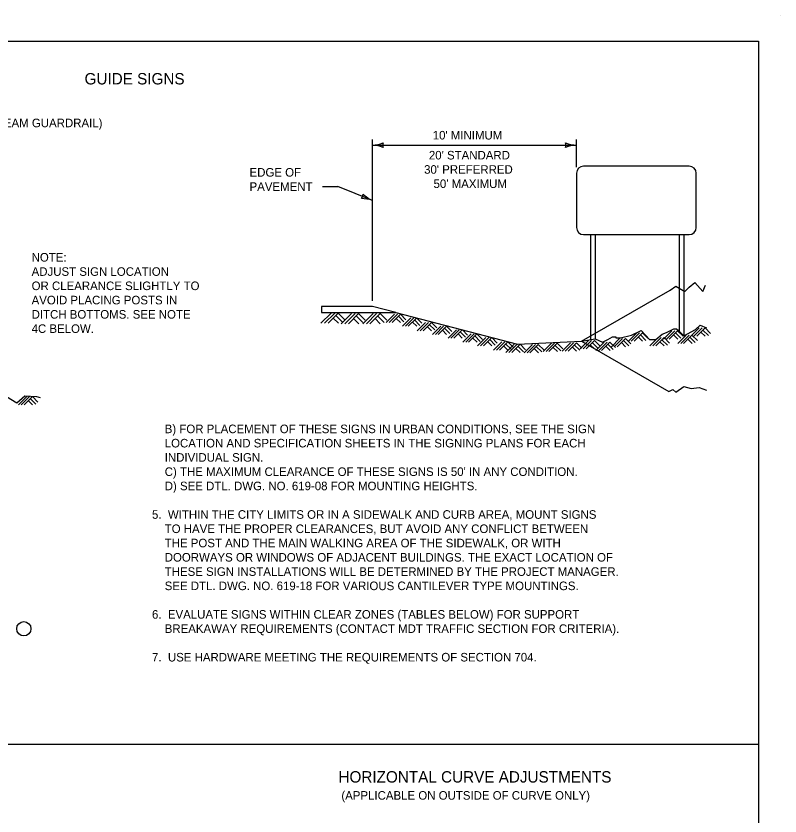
# Model space of a CAD drawing. Extents: x 49991.4 to 50021, y 49987.6 to 50011.4.
# Drawn here: x 50011.54 to 50016.9, y 49993.57 to 49999.18 of the extents above; entities that cross this region are included whole.
import ezdxf

# ---------------------------------------------------------------- set-up
doc = ezdxf.new("R2010")
doc.units = 0
for name, color, linetype in [('Level 1', 7, 'Continuous'), ('Level 2', 7, 'Continuous'), ('Level 3', 7, 'Continuous')]:
    doc.layers.add(name, color=color, linetype=linetype)

msp = doc.modelspace()

# ---------------------------------------------------------------- linework, layer by layer
at = {"layer": 'Level 1'}
for p, q in [((50016.9001, 49999.1756), (50016.9001, 49999.1756)), ((50016.263, 49998.1235), (50015.5229, 49998.1235)), ((50015.4729, 49998.0735), (50015.4729, 49997.6934)), ((50016.313, 49997.6934), (50016.313, 49998.0735)), ((50015.5229, 49997.6434), (50016.263, 49997.6434)), ((50015.5741, 49996.9115), (50015.5741, 49997.6434)), ((50015.6062, 49996.9147), (50015.6062, 49997.6434)), ((50016.1953, 49996.968), (50016.1953, 49997.6434)), ((50016.2274, 49996.9368), (50016.2274, 49997.6434)), ((50015.5091, 49996.8956), (50016.1291, 49997.2536)), ((50014.0419, 49997.1393), (50013.6857, 49997.1393)), ((50013.6857, 49997.1393), (50013.6857, 49997.0967)), ((50014.2056, 49997.0967), (50014.0419, 49997.1393)), ((50013.6806, 49997.022), (50013.7526, 49997.094)), ((50013.6857, 49997.0967), (50014.2058, 49997.0967)), ((50013.7059, 49997.022), (50013.7779, 49997.094)), ((50013.731, 49997.022), (50013.803, 49997.094)), ((50013.7853, 49997.0762), (50013.8321, 49997.0295)), ((50013.803, 49997.094), (50013.8499, 49997.0472)), ((50013.8231, 49997.019), (50013.8951, 49997.091)), ((50013.8484, 49997.019), (50013.9204, 49997.091)), ((50013.8735, 49997.019), (50013.9455, 49997.091)), ((50013.9455, 49997.091), (50013.9924, 49997.0442)), ((50013.9744, 49997.019), (50014.0464, 49997.091)), ((50013.9997, 49997.019), (50014.0717, 49997.091)), ((50014.0248, 49997.019), (50014.0968, 49997.091)), ((50014.0968, 49997.091), (50014.1437, 49997.0442)), ((50014.1395, 49997.0268), (50014.1978, 49997.0851)), ((50014.16, 49997.0268), (50014.2183, 49997.0851)), ((50014.1803, 49997.0268), (50014.2386, 49997.0851)), ((50014.2056, 49997.0967), (50014.2056, 49997.0967)), ((50014.2056, 49997.0967), (50015.0598, 49996.8746)), ((50014.2386, 49997.0851), (50014.2766, 49997.0472)), ((50013.7674, 49997.0583), (50013.8038, 49997.022)), ((50013.9099, 49997.0553), (50013.9463, 49997.019)), ((50013.9277, 49997.0732), (50013.9745, 49997.0265)), ((50014.0612, 49997.0553), (50014.0976, 49997.019)), ((50014.079, 49997.0732), (50014.1258, 49997.0265)), ((50014.2098, 49997.0563), (50014.2394, 49997.0268)), ((50014.2242, 49997.0708), (50014.2622, 49997.0329)), ((50014.2528, 49997.0015), (50014.3111, 49997.0598)), ((50014.2733, 49997.0015), (50014.3316, 49997.0598)), ((50014.2936, 49997.0015), (50014.3511, 49997.0589)), ((50014.3231, 49997.0309), (50014.3527, 49997.0015)), ((50014.3376, 49997.0455), (50014.3755, 49997.0076)), ((50014.3536, 49997.0582), (50014.3899, 49997.0219)), ((50014.3565, 49996.9699), (50014.4148, 49997.0282)), ((50014.377, 49996.9699), (50014.4353, 49997.0282)), ((50014.3973, 49996.9699), (50014.4556, 49997.0282)), ((50014.4556, 49997.0282), (50014.4936, 49996.9903)), ((50014.4268, 49996.9994), (50014.4563, 49996.9699)), ((50014.4413, 49997.0139), (50014.4792, 49996.976)), ((50014.4629, 49996.9437), (50014.5212, 49997.0021)), ((50014.4835, 49996.9437), (50014.5418, 49997.0021)), ((50014.5038, 49996.9437), (50014.5621, 49997.0021)), ((50014.5333, 49996.9731), (50014.5628, 49996.9437)), ((50014.5477, 49996.9877), (50014.5856, 49996.9498)), ((50014.5621, 49997.0021), (50014.6001, 49996.9641)), ((50014.5724, 49996.9186), (50014.6307, 49996.9769)), ((50014.5929, 49996.9186), (50014.6513, 49996.9769)), ((50014.6133, 49996.9186), (50014.6705, 49996.9758)), ((50014.6735, 49996.9751), (50014.7096, 49996.9391)), ((50016.0829, 49996.9118), (50016.1412, 49996.9701)), ((50016.1035, 49996.9118), (50016.1618, 49996.9701)), ((50016.1237, 49996.9118), (50016.1821, 49996.9701)), ((50016.1821, 49996.9701), (50016.2201, 49996.9322)), ((50016.2751, 49996.9309), (50016.3334, 49996.9892)), ((50016.2957, 49996.9309), (50016.354, 49996.9892)), ((50016.3159, 49996.9309), (50016.3743, 49996.9892)), ((50016.3599, 49996.9748), (50016.3978, 49996.937)), ((50016.3743, 49996.9892), (50016.4123, 49996.9513)), ((50014.6428, 49996.948), (50014.6722, 49996.9186)), ((50014.6572, 49996.9625), (50014.6951, 49996.9248)), ((50014.6759, 49996.8891), (50014.7342, 49996.9475)), ((50014.6965, 49996.8891), (50014.7548, 49996.9475)), ((50014.7167, 49996.8891), (50014.775, 49996.9475)), ((50014.7462, 49996.9186), (50014.7757, 49996.8891)), ((50014.7606, 49996.9331), (50014.7986, 49996.8952)), ((50014.775, 49996.9475), (50014.8131, 49996.9095)), ((50014.78, 49996.8635), (50014.8383, 49996.9218)), ((50014.8005, 49996.8635), (50014.8589, 49996.9218)), ((50014.8208, 49996.8635), (50014.879, 49996.9216)), ((50014.8795, 49996.9215), (50014.9172, 49996.8839)), ((50015.7175, 49996.8581), (50015.7758, 49996.9164)), ((50015.7381, 49996.8581), (50015.7964, 49996.9164)), ((50015.7583, 49996.8581), (50015.8167, 49996.9164)), ((50015.8167, 49996.9164), (50015.8547, 49996.8785)), ((50015.837, 49996.8963), (50015.8953, 49996.9546)), ((50015.8576, 49996.8963), (50015.9159, 49996.9546)), ((50015.8778, 49996.8963), (50015.9362, 49996.9546)), ((50015.9074, 49996.9257), (50015.9369, 49996.8963)), ((50015.9218, 49996.9402), (50015.9597, 49996.9024)), ((50015.9362, 49996.9546), (50015.9742, 49996.9167)), ((50015.9876, 49996.8633), (50016.0459, 49996.9216)), ((50016.0082, 49996.8633), (50016.0665, 49996.9216)), ((50016.0284, 49996.8633), (50016.0868, 49996.9216)), ((50016.0868, 49996.9216), (50016.1248, 49996.8837)), ((50016.1533, 49996.9412), (50016.1828, 49996.9118)), ((50016.1677, 49996.9557), (50016.2056, 49996.9179)), ((50016.1834, 49996.8807), (50016.2417, 49996.939)), ((50016.204, 49996.8807), (50016.2623, 49996.939)), ((50016.2242, 49996.8807), (50016.2826, 49996.939)), ((50016.2538, 49996.9101), (50016.2833, 49996.8807)), ((50016.2682, 49996.9246), (50016.3061, 49996.8868)), ((50016.2826, 49996.939), (50016.3206, 49996.9011)), ((50016.3455, 49996.9603), (50016.375, 49996.9309)), ((50014.8504, 49996.8929), (50014.8798, 49996.8635)), ((50014.8648, 49996.9074), (50014.9027, 49996.8696)), ((50014.8916, 49996.8339), (50014.9499, 49996.8922)), ((50014.9122, 49996.8339), (50014.9705, 49996.8922)), ((50014.9324, 49996.8339), (50014.9908, 49996.8922)), ((50014.962, 49996.8633), (50014.9915, 49996.8339)), ((50014.9764, 49996.8778), (50015.0143, 49996.84)), ((50014.9781, 49996.8167), (50015.0364, 49996.875)), ((50014.9908, 49996.8922), (50015.0288, 49996.8543)), ((50014.9987, 49996.8167), (50015.057, 49996.875)), ((50015.0189, 49996.8167), (50015.0773, 49996.875)), ((50015.0598, 49996.8746), (50015.5091, 49996.8956)), ((50015.0629, 49996.8606), (50015.1008, 49996.8228)), ((50015.0773, 49996.875), (50015.1153, 49996.8371)), ((50015.1063, 49996.8148), (50015.1646, 49996.8731)), ((50015.1269, 49996.8148), (50015.1852, 49996.8731)), ((50015.1471, 49996.8148), (50015.2055, 49996.8731)), ((50015.1911, 49996.8587), (50015.229, 49996.8209)), ((50015.2055, 49996.8731), (50015.2435, 49996.8352)), ((50015.2396, 49996.8236), (50015.2979, 49996.8819)), ((50015.2602, 49996.8236), (50015.3185, 49996.8819)), ((50015.2804, 49996.8236), (50015.3388, 49996.8819)), ((50015.31, 49996.853), (50015.3395, 49996.8236)), ((50015.3244, 49996.8675), (50015.3623, 49996.8297)), ((50015.3388, 49996.8819), (50015.3768, 49996.844)), ((50015.3729, 49996.827), (50015.4312, 49996.8853)), ((50015.3935, 49996.827), (50015.4518, 49996.8853)), ((50015.4137, 49996.827), (50015.4721, 49996.8853)), ((50015.4433, 49996.8564), (50015.4728, 49996.827)), ((50015.4577, 49996.8709), (50015.4956, 49996.8331)), ((50015.4721, 49996.8853), (50015.5101, 49996.8474)), ((50015.4993, 49996.8425), (50015.5576, 49996.9008)), ((50015.5091, 49996.8956), (50016.1195, 49996.5432)), ((50015.5199, 49996.8425), (50015.5782, 49996.9008)), ((50015.5401, 49996.8425), (50015.5985, 49996.9008)), ((50015.5697, 49996.8719), (50015.5992, 49996.8425)), ((50015.5841, 49996.8864), (50015.622, 49996.8486)), ((50015.5985, 49996.9008), (50015.6365, 49996.8629)), ((50015.6084, 49996.8322), (50015.6667, 49996.8905)), ((50015.629, 49996.8322), (50015.6873, 49996.8905)), ((50015.6492, 49996.8322), (50015.7076, 49996.8905)), ((50015.6788, 49996.8616), (50015.7083, 49996.8322)), ((50015.6932, 49996.8761), (50015.7311, 49996.8383)), ((50015.7076, 49996.8905), (50015.7456, 49996.8526)), ((50015.7879, 49996.8875), (50015.8174, 49996.8581)), ((50015.8023, 49996.902), (50015.8402, 49996.8642)), ((50016.058, 49996.8927), (50016.0875, 49996.8633)), ((50016.0724, 49996.9072), (50016.1103, 49996.8694)), ((50015.0485, 49996.8461), (50015.078, 49996.8167)), ((50015.1767, 49996.8442), (50015.2062, 49996.8148)), ((50011.5599, 49996.4495), (50011.6182, 49996.5079)), ((50011.5805, 49996.4495), (50011.6388, 49996.5079)), ((50011.6007, 49996.4495), (50011.659, 49996.5079)), ((50011.6302, 49996.479), (50011.6597, 49996.4495)), ((50011.6446, 49996.4935), (50011.6826, 49996.4556)), ((50011.659, 49996.5079), (50011.6971, 49996.4699))]:
    msp.add_line(p, q, dxfattribs=at)
msp.add_lwpolyline([(49999.3835, 49998.9992), (50016.7501, 49998.9992), (50016.7501, 49987.7988), (49999.3835, 49987.7988)], close=True, dxfattribs=at)
for points in [[(50016.1291, 49997.2536), (50016.1687, 49997.2819), (50016.2321, 49997.2438), (50016.2639, 49997.2755), (50016.3019, 49997.3072), (50016.359, 49997.2438), (50016.378, 49997.2882)], [(50015.5091, 49996.8956), (50015.6043, 49996.914), (50015.655, 49996.8886), (50015.6931, 49996.9076), (50015.7247, 49996.9267), (50015.7501, 49996.9267), (50015.7501, 49996.9204), (50015.7819, 49996.9204), (50015.8579, 49996.9394), (50015.9277, 49996.9711), (50015.9848, 49996.9076), (50016.0292, 49996.9076), (50016.0736, 49996.9457), (50016.1053, 49996.9584), (50016.156, 49996.9838), (50016.1751, 49996.9838), (50016.1878, 49996.9711), (50016.2258, 49996.933), (50016.3083, 49996.9774), (50016.3399, 49997.0092), (50016.3843, 49996.9901)], [(50016.1195, 49996.5432), (50016.1497, 49996.5588), (50016.1687, 49996.5398), (50016.2258, 49996.5779), (50016.2765, 49996.5652), (50016.3336, 49996.5715), (50016.3843, 49996.5524)], [(50011.1739, 49996.5018), (50011.2183, 49996.4891), (50011.2691, 49996.5144), (50011.3261, 49996.4954), (50011.4086, 49996.5081), (50011.4467, 49996.5271), (50011.5481, 49996.4637), (50011.6052, 49996.5144), (50011.6876, 49996.5081), (50011.7131, 49996.5017)]]:
    msp.add_lwpolyline(points, dxfattribs=at)
for centre, start, end in [((50015.5229, 49998.0735), 90, 180), ((50016.2629, 49998.0735), 0, 90), ((50015.5228, 49997.6934), 180, 270), ((50016.2629, 49997.6935), 270, 0)]:
    msp.add_arc(centre, 0.05, start, end, dxfattribs=at)
at = {"layer": 'Level 2'}
msp.add_circle((50011.5982, 49994.8813), 0.0501, dxfattribs=at)
at = {"layer": 'Level 3'}
for p, q in [((50014.0419, 49997.1793), (50014.0419, 49998.3101)), ((50015.4729, 49998.1151), (50015.4729, 49998.3101)), ((50014.0419, 49998.2701), (50015.4729, 49998.2701)), ((50013.6933, 49997.9799), (50013.7988, 49997.9799)), ((50014.0419, 49997.8836), (50013.7988, 49997.9799)), ((50008.0668, 49994.0732), (50016.7501, 49994.0732))]:
    msp.add_line(p, q, dxfattribs=at)
for centre, radius, start, end in [((50014.0304, 49998.5028), 0.233, 272.8273, 292.0772), ((50014.0327, 49998.048), 0.2223, 67.456, 87.6395), ((50014.1701, 49998.2701), 0.0548, 162.1388, 197.8612), ((50015.4821, 49998.4922), 0.2223, 247.456, 267.6395), ((50015.3447, 49998.2701), 0.0548, 342.1388, 17.8612), ((50015.4844, 49998.0374), 0.233, 92.8273, 112.0772), ((50013.9227, 49997.9308), 0.0548, 320.5287, 356.251), ((50014.1322, 49998.0867), 0.2223, 225.8458, 246.0294), ((50013.9669, 49997.663), 0.233, 71.2171, 90.467)]:
    msp.add_arc(centre, radius, start, end, dxfattribs=at)

# ---------------------------------------------------------------- texts
at = {"layer": 'Level 2'}
for s, height, p in [('GUIDE SIGNS', 0.08, (50012.0239, 49998.6959)), ("5' STANDARD (W-BEAM OR BOX BEAM GUARDRAIL)", 0.06, (50010.1459, 49998.396)), ("10' MINIMUM", 0.06, (50014.465, 49998.3101)), ("20' STANDARD", 0.06, (50014.4383, 49998.1701)), ('EDGE OF', 0.06, (50013.1809, 49998.0499)), ("30' PREFERRED", 0.06, (50014.4047, 49998.0701)), ("50' MAXIMUM", 0.06, (50014.471, 49997.9701)), ('PAVEMENT', 0.06, (50013.1809, 49997.9499)), ('NOTE:', 0.06, (50011.6528, 49997.4546)), ('ADJUST SIGN LOCATION', 0.06, (50011.6528, 49997.3546)), ('OR CLEARANCE SLIGHTLY TO', 0.06, (50011.6528, 49997.2546)), ('AVOID PLACING POSTS IN', 0.06, (50011.6528, 49997.1546)), ('DITCH BOTTOMS. SEE NOTE', 0.06, (50011.6528, 49997.0546)), ('4C BELOW.', 0.06, (50011.6528, 49996.9546)), ('    B) FOR PLACEMENT OF THESE SIGNS IN URBAN CONDITIONS, SEE THE SIGN', 0.06, (50012.4969, 49996.252)), ('    LOCATION AND SPECIFICATION SHEETS IN THE SIGNING PLANS FOR EACH', 0.06, (50012.4969, 49996.152)), ('    INDIVIDUAL SIGN.', 0.06, (50012.4969, 49996.052)), ("    C) THE MAXIMUM CLEARANCE OF THESE SIGNS IS 50' IN ANY CONDITION.", 0.06, (50012.4969, 49995.952)), ('    D) SEE DTL. DWG. NO. 619-08 FOR MOUNTING HEIGHTS.', 0.06, (50012.4969, 49995.852)), ('5.  WITHIN THE CITY LIMITS OR IN A SIDEWALK AND CURB AREA, MOUNT SIGNS', 0.06, (50012.4969, 49995.652)), ('    TO HAVE THE PROPER CLEARANCES, BUT AVOID ANY CONFLICT BETWEEN', 0.06, (50012.4969, 49995.552)), ('    THE POST AND THE MAIN WALKING AREA OF THE SIDEWALK, OR WITH', 0.06, (50012.4969, 49995.452)), ('    DOORWAYS OR WINDOWS OF ADJACENT BUILDINGS. THE EXACT LOCATION OF', 0.06, (50012.4969, 49995.352)), ('    THESE SIGN INSTALLATIONS WILL BE DETERMINED BY THE PROJECT MANAGER.', 0.06, (50012.4969, 49995.252)), ('    SEE DTL. DWG. NO. 619-18 FOR VARIOUS CANTILEVER TYPE MOUNTINGS.', 0.06, (50012.4969, 49995.152)), ('6.  EVALUATE SIGNS WITHIN CLEAR ZONES (TABLES BELOW) FOR SUPPORT', 0.06, (50012.4969, 49994.952)), ('    BREAKAWAY REQUIREMENTS (CONTACT MDT TRAFFIC SECTION FOR CRITERIA).', 0.06, (50012.4969, 49994.852)), ('7.  USE HARDWARE MEETING THE REQUIREMENTS OF SECTION 704.', 0.06, (50012.4969, 49994.652)), ('HORIZONTAL CURVE ADJUSTMENTS', 0.08, (50013.8044, 49993.8033)), ('(APPLICABLE ON OUTSIDE OF CURVE ONLY)', 0.06, (50013.8246, 49993.6833))]:
    msp.add_text(s, height=height, dxfattribs=at).set_placement(p)

doc.saveas('drawing.dxf')
